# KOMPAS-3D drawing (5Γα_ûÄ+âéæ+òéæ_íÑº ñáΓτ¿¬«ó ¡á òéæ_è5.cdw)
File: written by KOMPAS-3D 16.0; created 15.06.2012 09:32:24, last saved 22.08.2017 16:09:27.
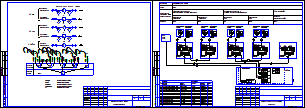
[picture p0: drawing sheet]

Sheets 1-2: A3, landscape

Title block, sheet 1: name: г. Москва, ул. Нежинская, д. 14, к.8 (кв. 1 и кв. 2); sheet number: 1; sheets: 27 / 28; sheet format: A3; stored path: D:\Проекты\Лыткарино\ул. Квартал 3А, д.25\710.74 РП.cdw; cell 320: Р
Title block, sheet 2: sheet number: 2

Views: Вид 2, Вид 3, Вид 4, Вид 5
Referenced files in C:\Program Files (x86)\ASCON\KOMPAS-3D V16\Sys\: SPDS.lcs, EngSys.lcs, GRAPHIC.LHS
Referenced files: graphic.tdp
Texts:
  МО, Клинский район, д. Решетниково, ул. Центральная, д.14
  GOST Common
  Normal
  List Paragraph
  heading 3
  для схемы
  txt
  краны
  Фоновая заливка
  Т0-элементы
  Агрегат
  Системный блок  МКТС
  Среда
  Вода
  параметра и место
  отбора импульса
  Учет тепловой энергии и
  теплоносителя системы отопления
  Подающий
  трубопровод
  отопления
  Обратный
  расхода горячей водысистемы ГВС
  Вводной
  трубопровод ХВС
  Узел учета ХВС
  ГВС
  ИМ1
  ИМ2
  ИМ3
  ИМ4
  ИМ5
  ВРУ
  Плата подключений
  СБ МКТС
  Pt 100
  Преобразователь
  температуры
  давления
  UP+
  UP-
  ИМП
  Лин
  Измерительный
  модуль М121
  каб.
  Начало
  трассы
  Трассы
  Марка
  Проложен
  Датчик температуры (Т1)
  Датчик температуры (Т2)
  Датчик температуры (Т3)
  Датчик температуры (Т4)
  Датчик давления (Т1)
  Датчик давления (Т2)
  Датчик давления (Т3)
  Изм. модуль (Т1)
  Датчик давления (Т4)
  Изм. модуль (Т2)
  Изм. модуль (Т3)
  Изм. модуль (Т4)
  Изм. модуль (В1)
  ВРУ 220В, 50 Гц
  ИМ1 УУТЭ
  ИМ2 УУТЭ
  ИМ2 УУГВС
  ИМ (Т1)
  ИМ (Т3)
  FTP
  ПВС
  Конец
  Кол-во и
  сеч. жил
  Длина,
  приборы
  по месту
  шкаф
  учета
  UQIES
  Преобразователь расхода
  Термопреобразователь
  Преобразователь давления
  Преобразователь цифровой
  Системный блок МКТС
  Функциональная схема
  УУГВС
  УУТЭ
  УУХВС
  Размеры, параметризация
  сит. план
  подача ГВС
  обратка ГВС
  хвс
  обратка
  POLYLINE_STYLE_0.25_RGB_0_0_0
  стены
  Основная (не является границей для штриховки)
  POLYLINE_STYLE_0.18_RGB_0_0_0
  ХВС
  зеленая
  Красная тонкая
  арматура
  Подача
  Скрытая линия
  Ось Z
  Ось Y
  Ось X
  Образующая трубопровода (проектируемого)
  Трубопровод толщиной 0.6мм (одна линия)
  Трубопровод толщиной 1.2мм (одна линия)
  Трубопровод толщиной 1.0мм (одна линия)
  Трубопровод толщиной 0.8мм (одна линия)
  Трубопровод существующий (одна линия)
  Трубопровод невидимый (одна линия)
  Трубопровод демонтируемый (одна линия)
  Осевая трубопровода
  Осевая трубопровода (демонтируемого)
  Образующая трубопровода (существующего)
  Образующая трубопровода (невидимого)
  Изолированный трубопровод проектируемый (одна линия)
  Изолированный трубопровод существующий (одна линия)
  Образующая изоляции
  Изоляция
  Изолированный трубопровод невидимый (одна линия)
  Штрих пвс 075
  штрих пвс 2,5
  существующее оборудование
  Существующее оборудование
  K5LT_BASIC_RGB_0_0_255_THICK_0.53
  POLYLINE_STYLE_1.51_RGB_0_0_255
  POLYLINE_STYLE_0.50_RGB_128_128_128
  K5LT_AXLED_RGB_255_128_0_SC_1_THICK_0.18
  ACAD_ISO04W100_RGB_0_0_0_SC_1_THICK_0.18
  тонкая черная
  пломбировка
  Провода
  синий штрих
  Стили документа
  G2co
  расход вторичной воды объемный
  расход вторичной воды объемный при 70гр
  Gco
  расход теплоносителя массовый
  расход теплоносит объемн подающ
  расход теплоносит объемн обр
  Лапир
  Ghvs
  Im1
  Im2
  Im3
  Im4
  Im5
  Khvs
  норматив ХВС
  число подъездов
  число этажей
  Nkv
  число квартир
  тепловая нагрузка на отопление
  сумма Q
  Qgvs
  тепловая нагрузка ГВС
  тепловая нагрузка на циркуляцию ГВС
  иммитовставка или под манометр
  ro1
  ro2
  ro3
  ro4
  верх предел темп граф
  нижн предел темп граф
  темп подачи ГВС
  темп обр ГВС
  темр хол воды
  vzdh
  Kchn
  Ktp
  Knp
  beta
  tnv
  Vклап
  KLP
  RPD
  RDS
  PUMP
  ro5
  Переход К-76 x 3-38 x 2-09Г2С ГОСТ 17378-2001
  Переход ГОСТ 17378-2001
  Переход
  ГОСТ
  Сталь 09Г2С ГОСТ 19281-89
  Переход К-76 x 3-45 x 2,5-09Г2С ГОСТ 17378-2001
  Переход К-57 x 3-38 x 2-09Г2С ГОСТ 17378-2001
  Переход К-57 x 3-32 x 2-09Г2С ГОСТ 17378-2001
  Втулка 20x50
  Переход К-108 x 4-57 x 3-09Г2С ГОСТ 17378-2001
  Переход К-45 x 2,5-32 x 2-09Г2С ГОСТ 17378-2001
  Переход К-89 x 3,5-45 x 2,5-09Г2С ГОСТ 17378-2001
  Переход К-133 x 5-108 x 4-09Г2С ГОСТ 17378-2001
  Переход К-159 x 4,5-89 x 3,5-09Г2С ГОСТ 17378-2001
  Переход К-45 x 2,5-38 x 2-09Г2С ГОСТ 17378-2001
  Фланец 1-32-1 Ст3сп ГОСТ 12820-80
  Фланцы
  Фланец
  квадратный
  Ст3сп
  Ст3сп ГОСТ 380-2005
  Переход К-57 x 3-45 x 2,5-09Г2С ГОСТ 17378-2001
  Переход К-76 x 3-57 x 3-09Г2С ГОСТ 17378-2001
  Фланец 1-50-16 Ст3сп ГОСТ 12821-80
  Переход К-89 x 3,5-76 x 3,5-09Г2С ГОСТ 17378-2001
  Переход К-108 x 4-89 x 3,5-09Г2С ГОСТ 17378-2001
  Тройник 159 x 4,5-09Г2С ГОСТ 17376-2001
  Тройники ГОСТ 17376-2001
  Тройник
  Отвод 90-159 x 4-09Г2С ГОСТ 17375-2001
  Отвод ГОСТ 17375-2001
  Отвод
  Переход К-108 x 4-76 x 3,5-09Г2С ГОСТ 17378-2001
  Переход К-159 x 4,5-108 x 4-09Г2С ГОСТ 17378-2001
  Переход К-133 x 5-76 x 3,5-09Г2С ГОСТ 17378-2001
  Переход К-133 x 4-89 x 3,5-09Г2С ГОСТ 17378-2001
  Переход К-1-42,4 x 2,6-21,3 x 2-TS10 ГОСТ 17378-2001
  TS10
  Сталь TS10 ИСО 2604/2-75
  Фланец 1-20-16 Ст3сп ГОСТ 12820-80
  Лит-Масса-Масштаб
  Материал-Предприятие
  Title Specification
  Body Specification ( left align )
  Body Specificaton ( centered )
  Поз.
  Кол.
  Приме-
  чание
  Таблица спецификации
  Засыпка
  Штрих3
  Штрих2
  Штрих1
  Песок
  Штр0.5пр7
  Штр0.5пр12
  Штр0.3пр10
  Штр1.4пр21.21
  Штр1пр15
  Штр2.12пр35
  Штр1.5пр25
  Штр2.82пр42.42
  Штр2пр30
  SACNCR_ISO 1
  Электрощитовая
  Пр-1
  Ок-1
  вапвыапвы
  Обозначение стандарта
  Типоразмер
  Разраб.
  Пров.
  Т.контр.
  Н.контр.
  Утв.
  автоматизации
  Рабочие чертежи основного комплекта. ГОСТ Р 21.1101-2009 Ф3
  Стадия
  Лист
  Листов
  Изм.
  Кол.уч.
  №док.
  Подп.
  Дата
  Изменение
  Номер документа
  Подпись
  Наименование объекта строительства, в состав которого входит здание, наим. микр
  Наименование здания (сооружения)
  Порядковый номер листа
  Количество листов в документе
  Наименование изображения
  Индекс предприятия, выпускающего документ
  Инв. № подл.
  Подп. и дата
  Взам. инв. №
  Инвентарный номер подлинника
  Подпись принявшего подлинник на хранение
  Инвентарный номер подлинника, взамен которого выпущен данный подлинник
  Согласовано
  Формат листа
  Согласование
  03 Рабочие чертежи основного комплекта. ГОСТ Р 21.1101-2009 Ф3
  Схема соединений внешних
  проводок
Dimensions and other numbers on the sheet: 0; 220В; 50Гц; 1; 2; 3; 6; 5; 4; 4-20; 2x2x0,52; 3х0,75; 15; 25; 11; 14; 19; 10; 7; 16; 60; 4,0; 2,6582; 0,0160; 95; 2,6160; 3,0; 0,7862; 0,0060; 70; 9; 12; 13; 8; 17; 0,4088; 50; 1,2,3,4,5; 6,7,8,9; 10,11,12,13; 14,15,16,17,18; 18; 0,0000; 09Г2С; 20; 21; 22; 23; 24; 26; 30; 31; 33; 34; 52; 64; 65; 66; 67; 69; 71; 72; 73; 74; 75; 27; 28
